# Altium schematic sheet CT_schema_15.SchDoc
size 385 x 278 mm
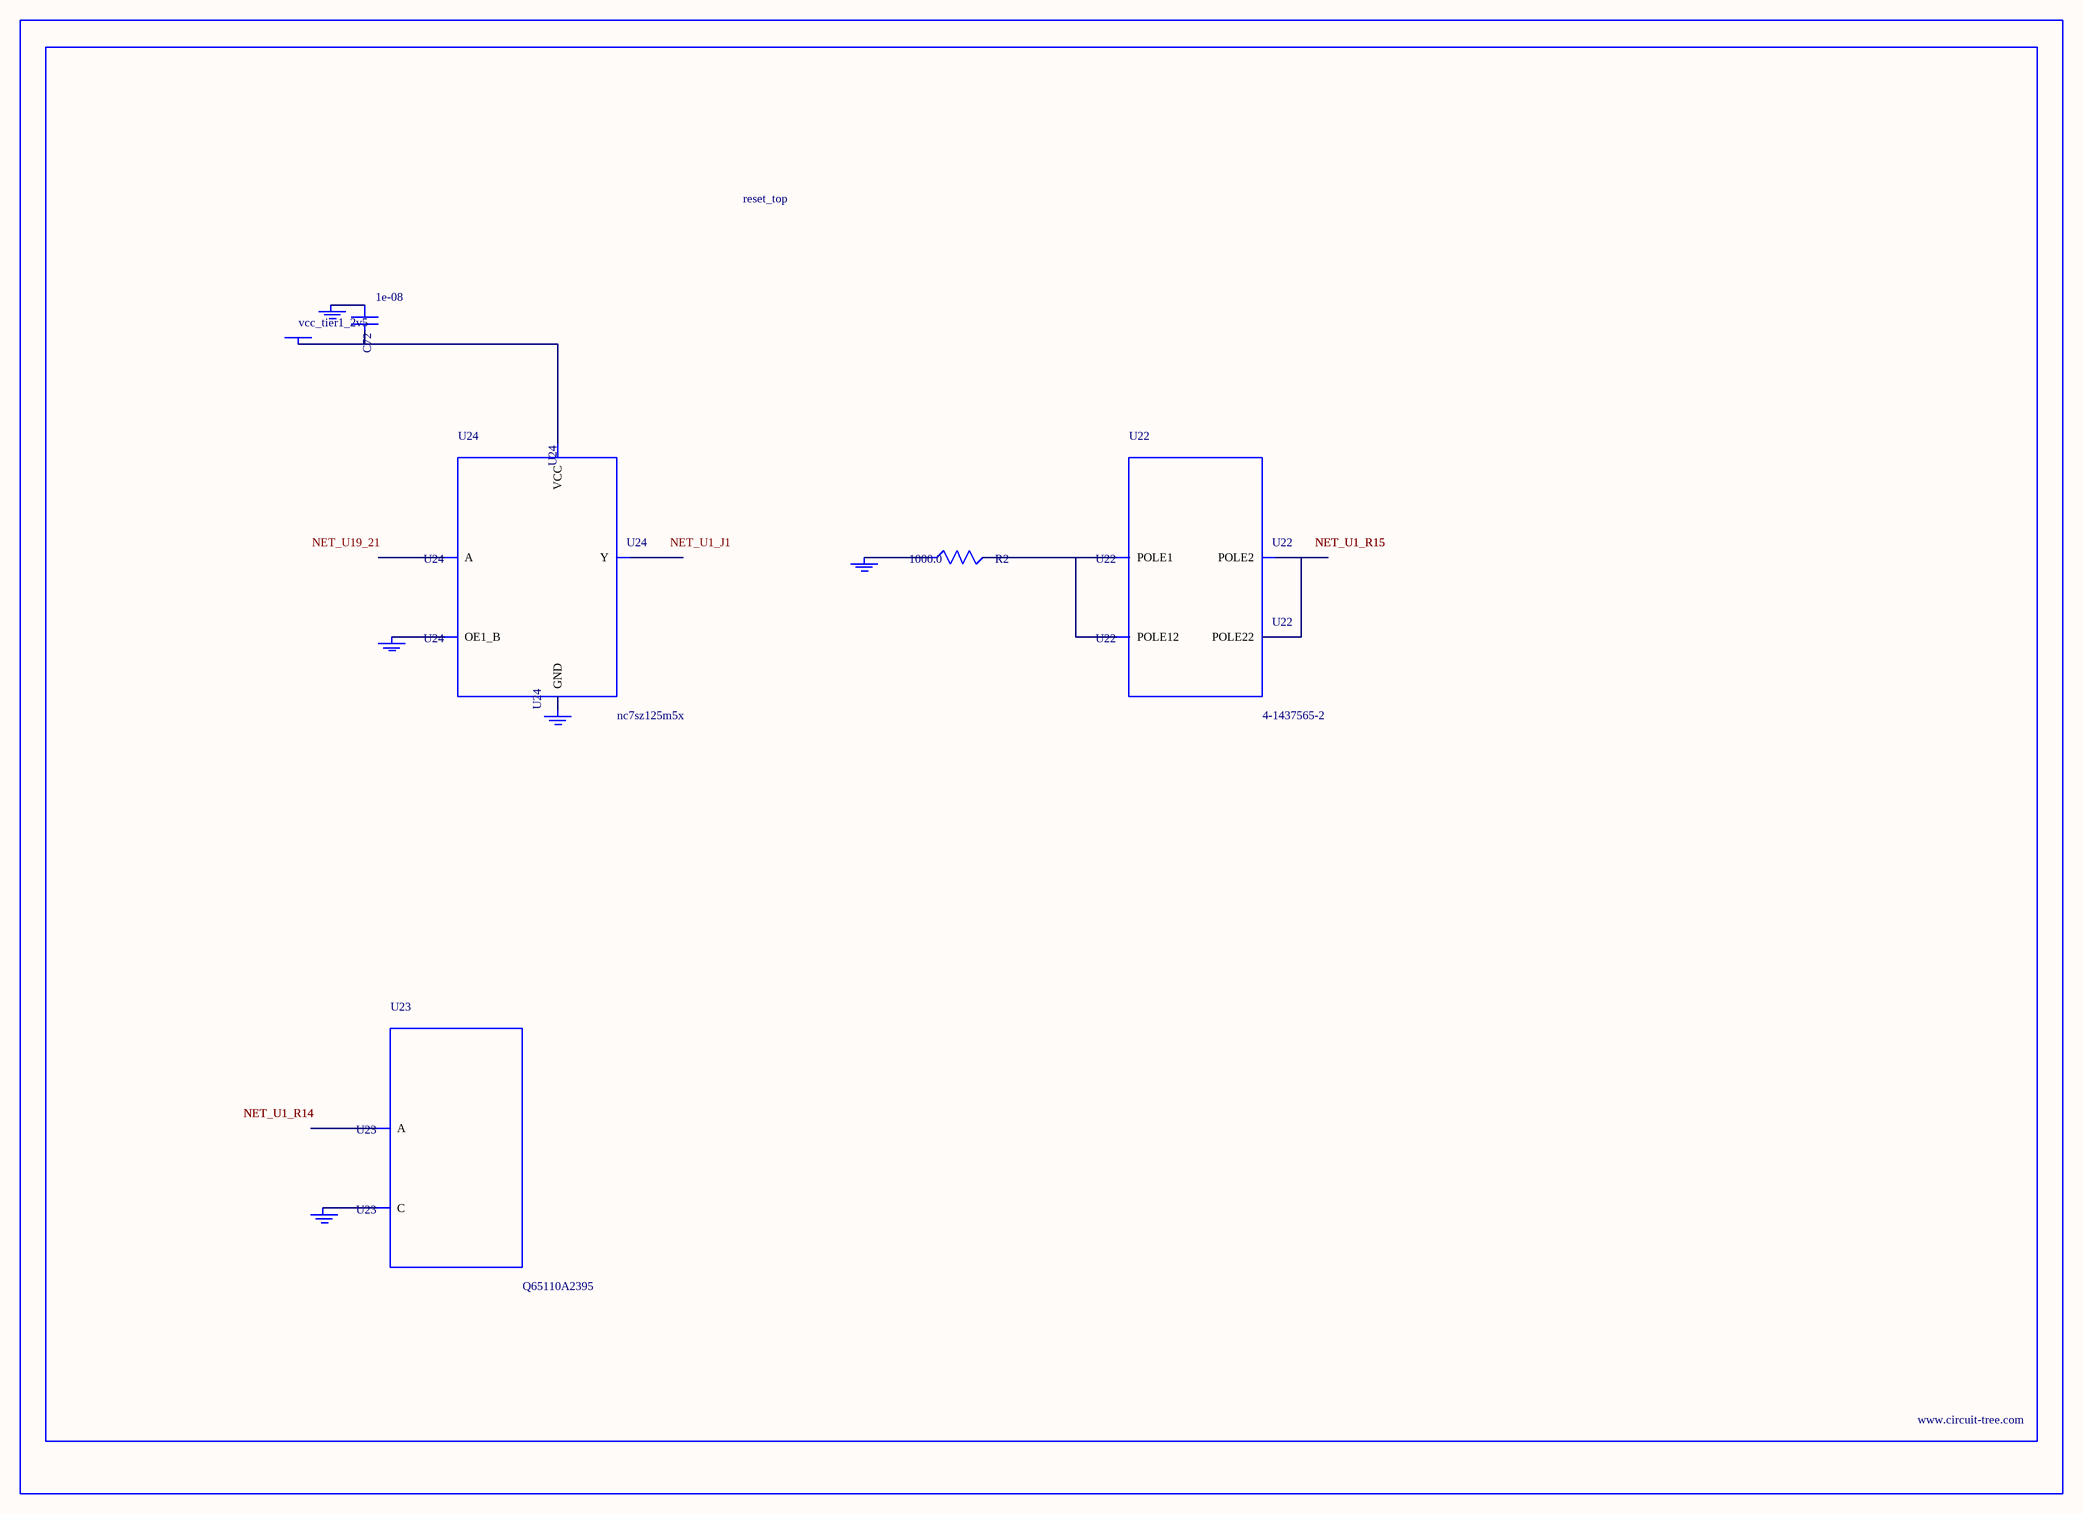
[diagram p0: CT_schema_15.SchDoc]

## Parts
BORDER14  (no value)
C72  1e-08  [C0402]
GND_INSTANCE_14_0  (no value)
GND_INSTANCE_14_1  (no value)
GND_INSTANCE_14_2  (no value)
GND_INSTANCE_14_3  (no value)
GND_INSTANCE_14_4  (no value)
POWER_INSTANCE_14_0  vcc_tier1_2v5
R2  1000.0  [R0603]
U22  4-1437565-2  [SW_4-1437565-2]
U23  Q65110A2395  [LGM67K-G1J2-24-Z]
U24  nc7sz125m5x  [NC7SZ125M5X]

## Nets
NetC72_1: C72.1 GND_INSTANCE_14_2.0(GND)
NetC72_2: C72.2 POWER_INSTANCE_14_0.0(PWR) U24.5(VCC)
NetGND_INSTANCE_14_0_0: GND_INSTANCE_14_0.0(GND) R2.1
NetGND_INSTANCE_14_1_0: GND_INSTANCE_14_1.0(GND) U23.C
NetGND_INSTANCE_14_3_0: GND_INSTANCE_14_3.0(GND) U24.1(OE1_B)
NetGND_INSTANCE_14_4_0: GND_INSTANCE_14_4.0(GND) U24.3(GND)
NetR2_2: R2.2 U22.1(POLE1) U22.2(POLE12)
NetU22_3: U22.3(POLE2) U22.4(POLE22)

Not connected (* = marked no-connect by the designer): U23 A; U24 2(A) 4(Y)

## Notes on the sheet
- Labels drawn without touching a wire or pin: NET_U1_J1, NET_U19_21

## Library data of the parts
BORDER14 = BORDER_PAGE14
C72 = C0402C103K3RAC
GND_INSTANCE_14_0-GND_INSTANCE_14_4 = GND
POWER_INSTANCE_14_0 = PWR
R2 = RC0603JR-071KL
